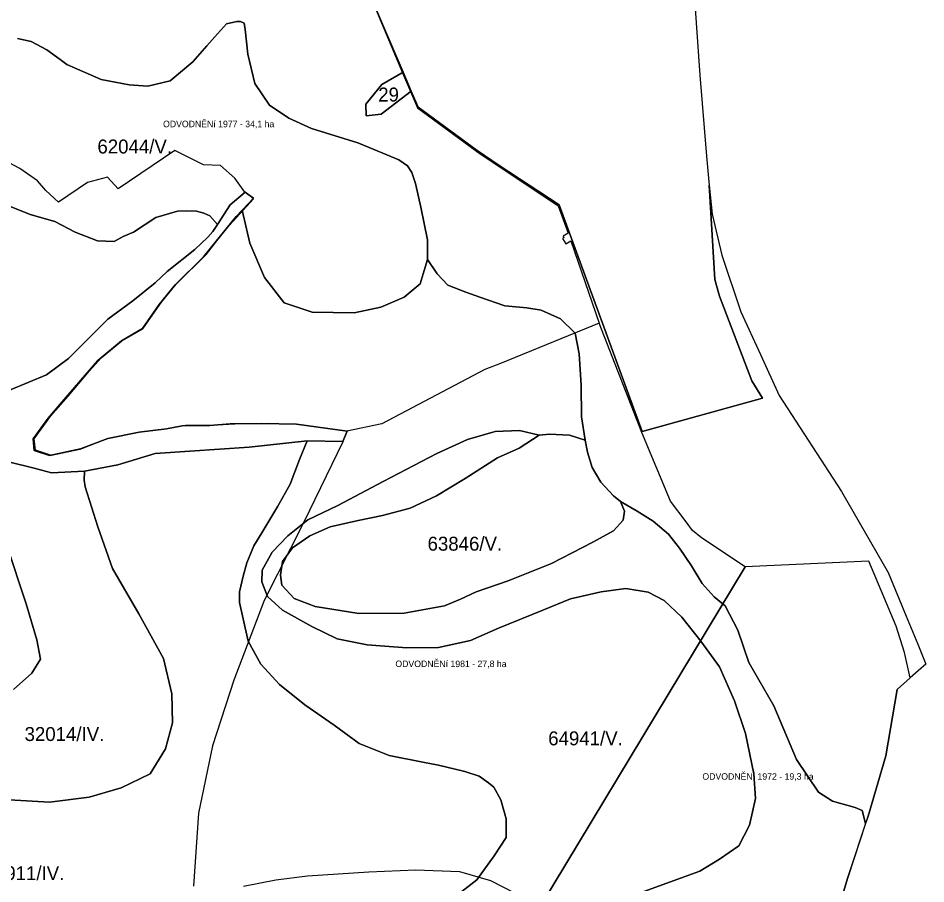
# Model space of a CAD drawing. Extents: x -521621 to -516761, y -1190184 to -1184927.
# Drawn here: x -517738 to -516761, y -1186934 to -1186003 of the extents above; entities that cross this region are included whole.
import ezdxf

# ---------------------------------------------------------------- set-up
doc = ezdxf.new("R2010")
doc.units = 0
doc.layers.add('BPEJ_s', color=7, linetype='Continuous')
doc.layers.add('odvodneni_s', color=7, linetype='Continuous')

msp = doc.modelspace()

# ---------------------------------------------------------------- linework, layer by layer
at = {"layer": 'BPEJ_s'}
for points in [[(-517010.1, -1185971.5), (-517003.7, -1186064.07), (-516996.45, -1186150.98), (-516994.45, -1186174.89), (-516993.72, -1186182.37), (-516987.52, -1186283.72), (-516982.63, -1186301.86), (-516947.67, -1186392.9), (-516936.44, -1186411.43), (-517065.71, -1186447.49), (-517155.08, -1186203.57), (-517219.62, -1186161.17), (-517243.4, -1186145.18), (-517307.11, -1186098.35), (-517314.39, -1186081.29), (-517323.17, -1186060.77), (-517357.41, -1185980.53)], [(-517357.41, -1185980.53), (-517323.17, -1186060.77), (-517346.12, -1186073.9), (-517363.45, -1186095), (-517362.87, -1186107.55), (-517346.82, -1186105.79), (-517314.39, -1186081.29), (-517307.11, -1186098.35), (-517243.4, -1186145.18), (-517219.62, -1186161.17), (-517155.08, -1186203.57), (-517065.71, -1186447.49), (-516936.44, -1186411.43), (-516947.67, -1186392.9), (-516982.63, -1186301.86), (-516987.52, -1186283.72), (-516993.72, -1186182.37), (-516990.65, -1186213.57), (-516980.18, -1186257.64), (-516959.79, -1186318.69), (-516938.61, -1186364.42), (-516918.56, -1186408.79), (-516851.25, -1186511.77), (-516801.06, -1186599.08), (-516781.74, -1186646.08), (-516769.31, -1186676.3), (-516760.51, -1186697.7), (-516768.82, -1186705.01), (-516777.29, -1186712.47), (-516791.41, -1186724.89), (-516803.7, -1186796.3), (-516822.77, -1186861.25), (-516825.38, -1186869.15), (-516829.21, -1186855.22), (-516831.48, -1186854.19), (-516836.66, -1186851.83), (-516861.06, -1186845.05), (-516875.97, -1186835.55), (-516899.69, -1186800.29), (-516924.09, -1186742.65), (-516951.2, -1186695.86), (-516962.72, -1186661.28), (-516976.61, -1186635), (-516988.47, -1186625.17), (-517001.35, -1186610.93), (-517012.87, -1186591.94), (-517025.74, -1186572.95), (-517037.6, -1186557.69), (-517053.87, -1186543.79), (-517071.15, -1186532.94), (-517089.11, -1186522.77), (-517096.56, -1186516.67), (-517110.46, -1186501.75), (-517119.6, -1186486.15), (-517124.69, -1186469.54), (-517127.1, -1186456.8), (-517131.06, -1186431.55), (-517131.56, -1186397.39), (-517133.54, -1186363.73), (-517137.99, -1186341.45), (-517153.82, -1186326.1), (-517174.6, -1186316.7), (-517189.94, -1186314.22), (-517213.69, -1186312.24), (-517240.41, -1186302.84), (-517255.74, -1186297.39), (-517275.04, -1186289.96), (-517286.42, -1186277.71), (-517296.81, -1186262.37), (-517296.81, -1186241.08), (-517304.23, -1186205.93), (-517309.67, -1186180.68), (-517313.88, -1186168.8), (-517318.33, -1186161.37), (-517327.73, -1186155.18), (-517345.05, -1186147.76), (-517371.76, -1186136.87), (-517421.73, -1186121.27), (-517446.23, -1186110.13), (-517466.93, -1186096.26), (-517482.76, -1186072.88), (-517490.3, -1186041.2), (-517493.32, -1186014.79), (-517494.36, -1186008.08), (-517498.08, -1186006.34), (-517502.05, -1186006.09), (-517513.21, -1186008.58), (-517522.88, -1186019.5), (-517534.29, -1186032.4), (-517549.66, -1186049.77), (-517573.72, -1186070.12), (-517597.78, -1186075.83), (-517618.11, -1186074.34), (-517648.12, -1186068.63), (-517685.08, -1186052.5), (-517692.37, -1186046.99), (-517706.57, -1186036.84), (-517723.47, -1186027.82), (-517738.12, -1186024.66)], [(-517738.12, -1186024.66), (-517723.47, -1186027.82), (-517706.57, -1186036.84), (-517692.37, -1186046.99), (-517685.08, -1186052.5), (-517648.12, -1186068.63), (-517618.11, -1186074.34), (-517597.78, -1186075.83), (-517573.72, -1186070.12), (-517549.66, -1186049.77), (-517534.29, -1186032.4), (-517522.88, -1186019.5), (-517513.21, -1186008.58), (-517502.05, -1186006.09), (-517498.08, -1186006.34), (-517494.36, -1186008.08), (-517493.32, -1186014.79), (-517490.3, -1186041.2), (-517482.76, -1186072.88), (-517466.93, -1186096.26), (-517446.23, -1186110.13), (-517421.73, -1186121.27), (-517371.76, -1186136.87), (-517345.05, -1186147.76), (-517327.73, -1186155.18), (-517318.33, -1186161.37), (-517313.88, -1186168.8), (-517309.67, -1186180.68), (-517304.23, -1186205.93), (-517296.81, -1186241.08), (-517296.81, -1186262.37), (-517301.51, -1186277.71), (-517304.86, -1186288.62), (-517322.2, -1186302.95), (-517347.08, -1186313.52), (-517375.72, -1186319.55), (-517420.95, -1186318.8), (-517451.1, -1186308.99), (-517472.21, -1186281.83), (-517488.04, -1186244.87), (-517496.31, -1186209.28), (-517484.2, -1186196.38), (-517490.27, -1186192.13), (-517493.11, -1186189.7), (-517509.15, -1186203.46), (-517523.01, -1186224.62), (-517531.1, -1186215.25), (-517537.55, -1186212.57), (-517545.7, -1186210.26), (-517556.05, -1186210.02), (-517566.15, -1186210.26), (-517589.4, -1186217.2), (-517613.25, -1186232.79), (-517624.45, -1186237.66), (-517634.19, -1186243.02), (-517652.2, -1186242.05), (-517676.05, -1186232.79), (-517697.96, -1186221.59), (-517724.74, -1186213.79), (-517745.18, -1186205.51)], [(-517764.3, -1186409.9), (-517707.01, -1186386.47), (-517683.18, -1186368.97), (-517641.06, -1186326.34), (-517614.21, -1186306.88), (-517590.12, -1186287.24), (-517577, -1186275.09), (-517547.29, -1186251.55), (-517533.17, -1186238.16), (-517527.97, -1186232.21), (-517523.01, -1186224.62), (-517509.15, -1186203.46), (-517493.11, -1186189.7), (-517490.27, -1186192.13), (-517484.2, -1186196.38), (-517496.31, -1186209.28), (-517502.72, -1186216.1), (-517538.12, -1186259.48), (-517568.42, -1186289.65), (-517585.67, -1186310.87), (-517603.75, -1186336.67), (-517626.4, -1186349.78), (-517651.79, -1186371.06), (-517683.59, -1186407.94), (-517705.32, -1186432.87), (-517721.22, -1186455.42), (-517720.43, -1186467.89), (-517703.73, -1186473.2), (-517670.34, -1186466.04), (-517640.92, -1186454.89), (-517607.26, -1186448), (-517577.84, -1186444.55), (-517560.94, -1186441.1), (-517531.12, -1186440.93), (-517509.23, -1186439.2), (-517475.61, -1186438.59), (-517437.97, -1186439.56), (-517383.38, -1186447.16), (-517388.06, -1186458.16), (-517426.51, -1186457.51), (-517488.89, -1186464.36), (-517552.65, -1186468.62), (-517589.98, -1186471.11), (-517630.35, -1186483.09), (-517666.23, -1186489.97), (-517701.52, -1186491.77), (-517720.36, -1186486.68), (-517747.87, -1186480.09)], [(-517745.18, -1186205.51), (-517724.74, -1186213.79), (-517697.96, -1186221.59), (-517676.05, -1186232.79), (-517652.2, -1186242.05), (-517634.19, -1186243.02), (-517624.45, -1186237.66), (-517613.25, -1186232.79), (-517589.4, -1186217.2), (-517566.15, -1186210.26), (-517556.05, -1186210.02), (-517545.7, -1186210.26), (-517537.55, -1186212.57), (-517531.1, -1186215.25), (-517523.01, -1186224.62), (-517527.97, -1186232.21), (-517533.17, -1186238.16), (-517547.29, -1186251.55), (-517577, -1186275.09), (-517590.12, -1186287.24), (-517614.21, -1186306.88), (-517641.06, -1186326.34), (-517683.18, -1186368.97), (-517707.01, -1186386.47), (-517764.3, -1186409.9)], [(-517269.81, -1186949.96), (-517243.89, -1186929.7), (-517225.25, -1186903.76), (-517212.29, -1186884.3), (-517212.29, -1186864.04), (-517217.96, -1186843.78), (-517225.66, -1186830.1), (-517231.13, -1186825.23), (-517241.46, -1186818.14), (-517256.64, -1186813.08), (-517285.2, -1186806.39), (-517299.98, -1186803.55), (-517338.26, -1186795.85), (-517370.46, -1186782.88), (-517397.19, -1186763.43), (-517428.78, -1186741.54), (-517456.33, -1186719.45), (-517476.38, -1186697.57), (-517489.95, -1186673.05), (-517495.41, -1186648.93), (-517499.26, -1186631.3), (-517499.26, -1186619.95), (-517495.41, -1186602.93), (-517491.36, -1186588.75), (-517483.67, -1186570.51), (-517475.16, -1186556.32), (-517458.15, -1186527.75), (-517444.58, -1186504.04), (-517434.86, -1186477.44), (-517426.51, -1186457.51), (-517388.06, -1186458.16), (-517383.38, -1186447.16), (-517437.97, -1186439.56), (-517475.61, -1186438.59), (-517509.23, -1186439.2), (-517531.12, -1186440.93), (-517560.94, -1186441.1), (-517577.84, -1186444.55), (-517607.26, -1186448), (-517640.92, -1186454.89), (-517670.34, -1186466.04), (-517703.73, -1186473.2), (-517720.43, -1186467.89), (-517721.22, -1186455.42), (-517705.32, -1186432.87), (-517683.59, -1186407.94), (-517651.79, -1186371.06), (-517626.4, -1186349.78), (-517603.75, -1186336.67), (-517585.67, -1186310.87), (-517568.42, -1186289.65), (-517538.12, -1186259.48), (-517502.72, -1186216.1), (-517496.31, -1186209.28), (-517488.04, -1186244.87), (-517472.21, -1186281.83), (-517451.1, -1186308.99), (-517420.95, -1186318.8), (-517375.72, -1186319.55), (-517347.08, -1186313.52), (-517322.2, -1186302.95), (-517304.86, -1186288.62), (-517301.51, -1186277.71), (-517296.81, -1186262.37), (-517286.42, -1186277.71), (-517275.04, -1186289.96), (-517255.74, -1186297.39), (-517240.41, -1186302.84), (-517213.69, -1186312.24), (-517189.94, -1186314.22), (-517174.6, -1186316.7), (-517153.82, -1186326.1), (-517137.99, -1186341.45), (-517133.54, -1186363.73), (-517131.56, -1186397.39), (-517131.06, -1186431.55), (-517127.1, -1186456.8), (-517143.93, -1186451.36), (-517165.7, -1186450.36), (-517176.58, -1186451.36), (-517197.86, -1186446.41), (-517224.08, -1186447.4), (-517253.76, -1186455.81), (-517286.91, -1186471.16), (-517344.54, -1186501.21), (-517393.56, -1186526.9), (-517425.77, -1186542.32), (-517447.25, -1186559.6), (-517464.06, -1186577.35), (-517474.8, -1186596.51), (-517475.26, -1186609.12), (-517469.2, -1186625.01), (-517452.85, -1186639.49), (-517421.57, -1186657.24), (-517394.03, -1186670.32), (-517361.81, -1186676.86), (-517319.33, -1186680.13), (-517285.24, -1186679.67), (-517250.69, -1186672.19), (-517220.35, -1186659.11), (-517172.72, -1186639.49), (-517142.84, -1186627.34), (-517110.16, -1186619.87), (-517083.55, -1186616.13), (-517059.27, -1186620.33), (-517042, -1186629.21), (-517023.32, -1186646.96), (-517002.78, -1186673.12), (-516982.7, -1186700.69), (-516966.36, -1186737.13), (-516954.69, -1186772.16), (-516945.82, -1186815.61), (-516943.95, -1186842.24), (-516950.49, -1186870.74), (-516961.69, -1186893.16), (-516982.7, -1186907.64), (-517003.71, -1186920.26), (-517063.94, -1186942.21)], [(-517063.94, -1186942.21), (-517003.71, -1186920.26), (-516982.7, -1186907.64), (-516961.69, -1186893.16), (-516950.49, -1186870.74), (-516943.95, -1186842.24), (-516945.82, -1186815.61), (-516954.69, -1186772.16), (-516966.36, -1186737.13), (-516982.7, -1186700.69), (-517002.78, -1186673.12), (-517023.32, -1186646.96), (-517042, -1186629.21), (-517059.27, -1186620.33), (-517083.55, -1186616.13), (-517110.16, -1186619.87), (-517142.84, -1186627.34), (-517172.72, -1186639.49), (-517220.35, -1186659.11), (-517250.69, -1186672.19), (-517285.24, -1186679.67), (-517319.33, -1186680.13), (-517361.81, -1186676.86), (-517394.03, -1186670.32), (-517421.57, -1186657.24), (-517452.85, -1186639.49), (-517469.2, -1186625.01), (-517475.26, -1186609.12), (-517474.8, -1186596.51), (-517464.06, -1186577.35), (-517447.25, -1186559.6), (-517425.77, -1186542.32), (-517393.56, -1186526.9), (-517344.54, -1186501.21), (-517286.91, -1186471.16), (-517253.76, -1186455.81), (-517224.08, -1186447.4), (-517197.86, -1186446.41), (-517176.58, -1186451.36), (-517198.35, -1186465.22), (-517221.6, -1186475.61), (-517256.3, -1186497.94), (-517287.11, -1186516.62), (-517315.59, -1186529.7), (-517345.47, -1186537.64), (-517371.62, -1186543.25), (-517401.5, -1186549.79), (-517423.44, -1186559.6), (-517442.12, -1186572.68), (-517452.85, -1186587.17), (-517455.19, -1186602.11), (-517453.79, -1186612.86), (-517440.25, -1186626.87), (-517417.84, -1186635.75), (-517370.68, -1186643.23), (-517322.13, -1186642.76), (-517278.71, -1186634.82), (-517261.43, -1186627.81), (-517244.64, -1186619.74), (-517210.08, -1186608.21), (-517163.32, -1186589.23), (-517118.93, -1186566.51), (-517096.56, -1186554.3), (-517086.4, -1186542.78), (-517085.04, -1186532.94), (-517089.11, -1186522.77), (-517071.15, -1186532.94), (-517053.87, -1186543.79), (-517037.6, -1186557.69), (-517025.74, -1186572.95), (-517012.87, -1186591.94), (-517001.35, -1186610.93), (-516988.47, -1186625.17), (-516976.61, -1186635), (-516962.72, -1186661.28), (-516951.2, -1186695.86), (-516924.09, -1186742.65), (-516899.69, -1186800.29), (-516875.97, -1186835.55), (-516861.06, -1186845.05), (-516836.66, -1186851.83), (-516831.48, -1186854.19), (-516829.21, -1186855.22), (-516825.38, -1186869.15), (-516844.56, -1186927.14), (-516850.39, -1186946.24)], [(-517747.01, -1186843.76), (-517703.63, -1186846.04), (-517661.02, -1186840.71), (-517626.77, -1186830.81), (-517595.57, -1186815.58), (-517578.83, -1186788.93), (-517571.22, -1186760.76), (-517571.98, -1186729.54), (-517581.12, -1186691.47), (-517607.75, -1186643.5), (-517635.9, -1186594.77), (-517651.88, -1186549.84), (-517665.22, -1186506.92), (-517666.57, -1186499.7), (-517666.23, -1186489.97), (-517630.35, -1186483.09), (-517589.98, -1186471.11), (-517552.65, -1186468.62), (-517488.89, -1186464.36), (-517426.51, -1186457.51), (-517434.86, -1186477.44), (-517444.58, -1186504.04), (-517458.15, -1186527.75), (-517475.16, -1186556.32), (-517483.67, -1186570.51), (-517491.36, -1186588.75), (-517495.41, -1186602.93), (-517499.26, -1186619.95), (-517499.26, -1186631.3), (-517495.41, -1186648.93), (-517489.95, -1186673.05), (-517476.38, -1186697.57), (-517456.33, -1186719.45), (-517428.78, -1186741.54), (-517397.19, -1186763.43), (-517370.46, -1186782.88), (-517338.26, -1186795.85), (-517299.98, -1186803.55), (-517285.2, -1186806.39), (-517256.64, -1186813.08), (-517241.46, -1186818.14), (-517231.13, -1186825.23), (-517225.66, -1186830.1), (-517217.96, -1186843.78), (-517212.29, -1186864.04), (-517212.29, -1186884.3), (-517225.25, -1186903.76), (-517243.89, -1186929.7), (-517269.81, -1186949.96)], [(-517747.87, -1186480.09), (-517720.36, -1186486.68), (-517701.52, -1186491.77), (-517666.23, -1186489.97), (-517666.57, -1186499.7), (-517665.22, -1186506.92), (-517651.88, -1186549.84), (-517635.9, -1186594.77), (-517607.75, -1186643.5), (-517581.12, -1186691.47), (-517571.98, -1186729.54), (-517571.22, -1186760.76), (-517578.83, -1186788.93), (-517595.57, -1186815.58), (-517626.77, -1186830.81), (-517661.02, -1186840.71), (-517703.63, -1186846.04), (-517747.01, -1186843.76)], [(-517742.44, -1186724.97), (-517722.65, -1186707.46), (-517713.52, -1186692.23), (-517717.33, -1186671.67), (-517728.74, -1186632.84), (-517750.05, -1186568.88)], [(-517750.05, -1186568.88), (-517728.74, -1186632.84), (-517717.33, -1186671.67), (-517713.52, -1186692.23), (-517722.65, -1186707.46), (-517742.44, -1186724.97)]]:
    msp.add_lwpolyline(points, dxfattribs=at)
for points in [[(-517323.17, -1186060.77), (-517314.39, -1186081.29), (-517346.82, -1186105.79), (-517362.87, -1186107.55), (-517363.45, -1186095), (-517346.12, -1186073.9)], [(-517176.58, -1186451.36), (-517165.7, -1186450.36), (-517143.93, -1186451.36), (-517127.1, -1186456.8), (-517124.69, -1186469.54), (-517119.6, -1186486.15), (-517110.46, -1186501.75), (-517096.56, -1186516.67), (-517089.11, -1186522.77), (-517085.04, -1186532.94), (-517086.4, -1186542.78), (-517096.56, -1186554.3), (-517118.93, -1186566.51), (-517163.32, -1186589.23), (-517210.08, -1186608.21), (-517244.64, -1186619.74), (-517261.43, -1186627.81), (-517278.71, -1186634.82), (-517322.13, -1186642.76), (-517370.68, -1186643.23), (-517417.84, -1186635.75), (-517440.25, -1186626.87), (-517453.79, -1186612.86), (-517455.19, -1186602.11), (-517452.85, -1186587.17), (-517442.12, -1186572.68), (-517423.44, -1186559.6), (-517401.5, -1186549.79), (-517371.62, -1186543.25), (-517345.47, -1186537.64), (-517315.59, -1186529.7), (-517287.11, -1186516.62), (-517256.3, -1186497.94), (-517221.6, -1186475.61), (-517198.35, -1186465.22)]]:
    msp.add_lwpolyline(points, close=True, dxfattribs=at)
at = {"layer": 'odvodneni_s'}
for points in [[(-517358.73, -1185978.4), (-517323.88, -1186061.41), (-517315.26, -1186081.51), (-517315.26, -1186081.51), (-517307.69, -1186099.15), (-517240.3, -1186148.46), (-517156.28, -1186204.57), (-517145.46, -1186233.96), (-517150.84, -1186237.35), (-517150.08, -1186238.88), (-517151.51, -1186239.83), (-517147.98, -1186245.42), (-517142.59, -1186242.13), (-517112.03, -1186330.95), (-517218.36, -1186374.05), (-517235.08, -1186380.83), (-517345.97, -1186439.2), (-517383.7, -1186447.12), (-517411.33, -1186443.42), (-517436.4, -1186439.95), (-517468.66, -1186438.71), (-517497.83, -1186439.1), (-517529.62, -1186440.87), (-517557.32, -1186440.8), (-517578.92, -1186444.89), (-517606.78, -1186448.13), (-517640.88, -1186455.07), (-517670.98, -1186466.65), (-517701.69, -1186473.28), (-517718.97, -1186467.49), (-517720.21, -1186455.38), (-517702.38, -1186430.46), (-517683.56, -1186409.31), (-517660.64, -1186382.23), (-517648.14, -1186368.11), (-517625.84, -1186349.9), (-517603.15, -1186336.94), (-517583.24, -1186308.31), (-517567.27, -1186288.86), (-517534.71, -1186256.46), (-517513.57, -1186229.14), (-517484.26, -1186196.91), (-517484.26, -1186196.91), (-517490.08, -1186192.36), (-517493.51, -1186189.68), (-517504.21, -1186174.93), (-517519.54, -1186161.33), (-517537.91, -1186160.61), (-517568.71, -1186144.85), (-517629.88, -1186186.21), (-517641.45, -1186173.77), (-517662.85, -1186179.41), (-517694.23, -1186200.67), (-517707.83, -1186188.23), (-517716.65, -1186177.67), (-517735.74, -1186164.22), (-517759.02, -1186152.37)], [(-517494.86, -1186936.67), (-517460.04, -1186929.71), (-517426.19, -1186925.39), (-517360.16, -1186921.07), (-517309.5, -1186919.15), (-517262.43, -1186920.59), (-517229.06, -1186930.43), (-517175.45, -1186958.22), (-516954.83, -1186592.8), (-517002.05, -1186561.79), (-517011.76, -1186553.99), (-517018.44, -1186544.45), (-517035.44, -1186522.2), (-517066.22, -1186448.33), (-517112.03, -1186330.95), (-517218.36, -1186374.05), (-517235.08, -1186380.83), (-517345.97, -1186439.2), (-517383.7, -1186447.12), (-517388.18, -1186458.31), (-517430.14, -1186544.79), (-517472.86, -1186629.05), (-517505.29, -1186714.91), (-517528.19, -1186785.51), (-517543.45, -1186858.01), (-517548.94, -1186936.72)]]:
    msp.add_lwpolyline(points, dxfattribs=at)
msp.add_lwpolyline([(-516954.83, -1186592.8), (-517175.45, -1186958.22), (-517134.87, -1186982.42), (-516976.29, -1187062.17), (-516877.08, -1186998.25), (-516871.88, -1187016.23), (-516856.6, -1186966.47), (-516850.39, -1186946.24), (-516844.56, -1186927.14), (-516822.77, -1186861.25), (-516803.7, -1186796.3), (-516791.41, -1186724.89), (-516777.29, -1186712.47), (-516783.52, -1186685.16), (-516792.51, -1186656.77), (-516821.91, -1186586.88)], close=True, dxfattribs=at)

# ---------------------------------------------------------------- texts
at = {"layer": 'BPEJ_s'}
for s, p in [('29', (-517349.95, -1186092.31)), ('62044/V.', (-517652.2, -1186148.24)), ('63846/V.', (-517296.84, -1186575.57)), ('32014/IV.', (-517730.61, -1186780.37)), ('64941/V.', (-517166.97, -1186785.01)), ('34911/IV.', (-517773.65, -1186930.07))]:
    msp.add_text(s, height=15, dxfattribs=at).set_placement(p)
at = {"layer": 'odvodneni_s'}
for s, p in [('ODVODNĚNí 1977 - 34,1 ha', (-517581.53, -1186119.98)), ('ODVODNĚNí 1981 - 27,8 ha', (-517331.48, -1186700.83)), ('ODVODNĚNí 1972 - 19,3 ha', (-517001.01, -1186822.03))]:
    msp.add_text(s, height=7, dxfattribs=at).set_placement(p)

doc.saveas('drawing.dxf')
